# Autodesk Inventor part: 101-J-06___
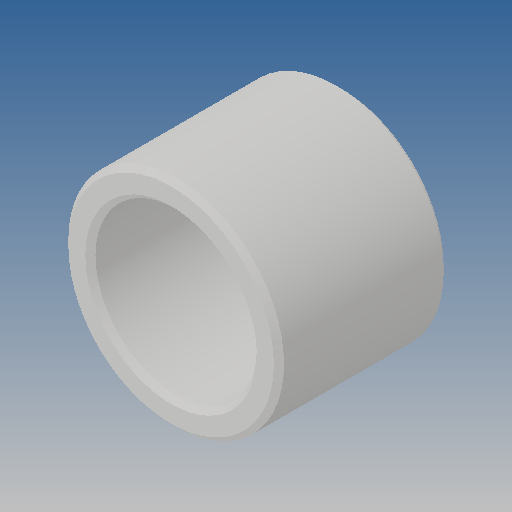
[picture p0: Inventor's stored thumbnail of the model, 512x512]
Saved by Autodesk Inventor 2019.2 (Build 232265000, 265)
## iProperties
Created: 2010-06
Part Number: 101-J-06___
Material: Ogólny
Document SubType Name: Modeling
Designer: CADENGINEERING4
Density: 1 g/cm^3
Appearance: Domyślna
Author: CADENGINEERING4
Revision Number: ANY
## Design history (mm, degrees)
feature "NONE"
node "Bryła1"
